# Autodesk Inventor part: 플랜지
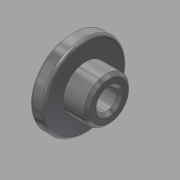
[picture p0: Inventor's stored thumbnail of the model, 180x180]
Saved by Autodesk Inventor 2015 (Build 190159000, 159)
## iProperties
Created: 2018-01
Part Number: 플랜지
Material: 스테인리스강
Document SubType Name: Modeling
Designer: mduedu
Density: 8.08 g/cm^3
Appearance: 반광택
Mass: 3.95967 g
Surface Area: 5.35087 cm^2
Volume: 0.490059 cm^3
Author: mduedu
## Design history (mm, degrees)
sketch "스케치1"
  geometry: L1 (0, 0)-(0, 7); L2 (0, 7)-(2.5, 7); L3 (2.5, 7)-(2.5, 3.75); L4 (2.5, 3.75)-(6.5, 3.75); L5 (6.5, 3.75)-(6.5, 0); L6 (6.5, 0)-(0, 0)
  constraints: 12 end point, 4 parallel, 1 perpendicular, 1 vertical
  dimensions: "d0" = 14 diameter of L2 L6; "d2" = 7.5 diameter of L4 L6; "d3" = 2.5 distance of L1.end L2.end; "d4" = 6.5 distance between parallel lines of L5 L1
revolve "회전1" sketch "스케치1" stored, may be unused: angle "d5" = 90 deg
hole "구멍1" diameter "d8" = 3.5; stored, may be unused: countersink angle "d12" = 90 deg, drill point angle "d14" = 118 deg; dims "d9" = 6, "d10" = 4, "d11" = 2, "d13" = 8, "d19" = 10, "d20" = 10
fillet "모깎기1" dims "d15" = 0.5
chamfer "모따기1" distance "d16" = 0.5; stored, may be unused: second distance "d17" = 2, angle "d18" = 45 deg
chamfer "모따기2" distance "d21" = 0.5; stored, may be unused: second distance "d22" = 2, angle "d23" = 45 deg
node "솔리드1"
